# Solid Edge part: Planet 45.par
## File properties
Title: Planet 45
Author: DESYS
Template: Normal.par
Last saved by: PIM_1
Revision: 18
Application: Solid Edge
Tipo di contenuto documento: 0
Precisione: 0,990
Document Number: 8100
Revision: 0
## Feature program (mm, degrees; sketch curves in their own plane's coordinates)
sketch for "unnamed RevolvedProtrusion 1" plane through (0, 0, 0) normal (1, 0, 0) x-axis (0, 1, 0)
  line (0, 0) -> (-150, 0)
  arc centre (204.6477, -225) radius 420 from (-150, 0) to (-150, -450) ccw
  line (0, -450) -> (-150, -450)
revolve "unnamed RevolvedProtrusion 1" add full turn 360 deg about sketch line (0, -450) -> (0, 0)
sketch for "unnamed Cutout 1" plane through (0, 0, 0) normal (1, 0, 0) x-axis (0, 1, 0)
  line (-150, 0) -> (256.3931, -170)
extrude "unnamed Cutout 1" cut through
sketch for "unnamed Cutout 2" plane through (0, 0, 0) normal (1, 0, 0) x-axis (0, 1, 0)
  line (-289.0701, -170) -> (150, -450)
  dimension (linear) = 289.0701
extrude "unnamed Cutout 2" cut through
lofted cutout "unnamed LoftedCutout 1"
sketch for "ExtrudedProtrusion_1" plane through (0, 0, -20) normal (0, 0, 1) x-axis (1, 0, 0)
  line (115, -240) -> (115, -111.0081)
  line (-115, -240) -> (115, -240)
  line (-115, -240) -> (-115, -111.0081)
  dimension (linear) = 115
extrude "ExtrudedProtrusion_1" add finite 269.9862 along -normal
sketch for "Foro_1" plane through (0, -204.5382, -20) normal (0, 0, 1) x-axis (0, 1, 0)
  hole centre (14.5382, 0) bore radius 17.5
hole "Foro_1" diameter 35 through
sketch for "ExtrudedCutout_3" plane through (0, 0, 0) normal (1, 0, 0) x-axis (0, 1, 0)
  line (31.771, -213.9421) -> (95.2508, -415.0858)
  line (-99.0796, -213.9421) -> (31.771, -213.9421)
  line (-145, -35) -> (-99.0796, -213.9421)
  line (-225, -35) -> (-145, -35)
  line (-225, -35) -> (-225, -249.6187)
  dimension (linear) = 225
extrude "ExtrudedCutout_3" cut finite 190 symmetric
sketch for "unnamed Cutout 3" plane through (115, -197.1931, -174.9931) normal (1, 0, 0) x-axis (0, 1, 0)
  line (356.26, -280.789) -> (15.3699, -63.3995)
  arc centre (-193.0261, -211.6399) radius 255.7423 from (15.3699, -63.3995) to (-42.8069, -4.6657) ccw
extrude "unnamed Cutout 3" cut through along -normal
fillet "Rotondo_2" radius 90
fillet "Rotondo_3" radius 50
fillet "Rotondo_4" radius 15
sketch for "ExtrudedProtrusion_2" plane through (0, -43.9675, -213.9421) normal (0, 0, -1) x-axis (0, 1, 0)
  circle centre (-6.0325, 0) radius 35
extrude "ExtrudedProtrusion_2" add finite 80 along +normal
sketch for "ExtrudedCutout_6" plane through (0, -50, -293.9421) normal (0, 0, -1) x-axis (1, 0, 0)
  circle centre (0, 0) radius 24.5286
extrude "ExtrudedCutout_6" cut finite 800 along -normal
fillet "Rotondo_6" radius 15
sketch for "ExtrudedProtrusion_3" plane through (0, 0, 0) normal (1, 0, 0) x-axis (0, 1, 0)
  line (-91.9423, -267.0478) -> (-78.5367, -268.9499)
  line (-80.6987, -208.2144) -> (-78.5367, -268.9499)
  line (-121.1922, -30.6357) -> (-80.6987, -208.2144)
  line (-158.0507, -30.6357) -> (-121.1922, -30.6357)
  line (-158.0507, -30.6357) -> (-125.8286, -233.7128)
  arc centre (-86.3228, -227.4445) radius 40 from (-125.8286, -233.7128) to (-91.9423, -267.0478) ccw
extrude "ExtrudedProtrusion_3" add finite 40 symmetric
sketch for "unnamed Cutout 4" plane through (0, -240, -122.9938) normal (0, -1, 0) x-axis (1, 0, 0)
extrude "unnamed Cutout 4" cut through
sketch for "unnamed Cutout 5" #1 plane through (0, -240, -122.9938) normal (0, -1, 0) x-axis (1, 0, 0)
  line (60, 62.9938) -> (60, 72.9938)
  line (40, 72.9938) -> (40, 62.9938)
sketch for "unnamed Cutout 5" #2 plane through (0, -240, -122.9938) normal (0, -1, 0) x-axis (1, 0, 0)
  line (-50, 62.9938) -> (-40, 62.9938)
  line (-40, 82.9938) -> (-50, 82.9938)
  dimension (linear) = 50
  dimension (linear) = 50
extrude "unnamed Cutout 5" cut through along -normal
sketch for "ExtrudedCutout_9" plane through (-0.1325, -39.6447, -329.0615) normal (0, -0.537684, -0.843146) x-axis (0, 0.843146, -0.537684)
  line (-169.9069, -114.8675) -> (-10.3347, -114.8675)
  bspline degree 3 poles (149.8015, -4.8675) (149.8046, -12.0052) (148.8083, -19.4097) (144.5593, -34.1545) (141.3116, -41.4824) (132.668, -55.503) (127.277, -62.1951) (114.6742, -74.5758) (107.4624, -80.2644) (91.669, -90.4075) (83.0852, -94.863) (65.099, -102.4153) (55.6967, -105.5121) (36.6563, -110.3534) (27.018, -112.0979) (8.0292, -114.3547) (-1.3214, -114.867) (-10.3347, -114.8675) knots 0 0.125 0.25 0.375 0.5 0.625 0.75 0.875 1 multiplicities 4 2 2 2 2 2 2 2 4
  line (149.8015, 5.1325) -> (149.8015, -4.8675)
  bspline degree 3 poles (-10.3347, 115.1325) (-1.3214, 115.132) (8.0292, 114.6197) (27.018, 112.3629) (36.6563, 110.6184) (55.6967, 105.777) (65.099, 102.6803) (83.0852, 95.1279) (91.669, 90.6724) (107.4624, 80.5294) (114.6742, 74.8407) (127.277, 62.46) (132.668, 55.768) (141.3116, 41.7473) (144.5593, 34.4195) (148.8083, 19.6747) (149.8046, 12.2701) (149.8015, 5.1325) knots 0 0.125 0.25 0.375 0.5 0.625 0.75 0.875 1 multiplicities 4 2 2 2 2 2 2 2 4
  line (-169.9069, 115.1325) -> (-10.3347, 115.1325)
  line (-169.9069, 115.1325) -> (-169.9069, 220.6808)
  line (-169.9069, 220.6808) -> (238.9114, 220.6808)
  line (238.9114, 220.6808) -> (234.9328, -219.2448)
  line (-169.9069, -219.2448) -> (234.9328, -219.2448)
  line (-169.9069, -114.8675) -> (-169.9069, -219.2448)
extrude "ExtrudedCutout_9" cut finite 10 along -normal
sketch for "Foro_3" plane through (0, 0, 0) normal (0, -1, 0) x-axis (1, 0, 0)
  hole centre (0, -140) bore radius 10
hole "Foro_3" diameter 20 finite
fillet "Rotondo_8" radius 10
fillet "Rotondo_10" radius 8
fillet "Rotondo_11" radius 8
fillet "Rotondo_12" radius 8
fillet "Rotondo_13" radius 6
fillet "Rotondo_16" radius 3
fillet "Rotondo_17" radius 5
fillet "Rotondo_18" radius 5
fillet "Rotondo_19" radius 10
fillet "Rotondo_20" radius 10
fillet "Rotondo_21" radius 5
sketch for "unnamed RevolvedCutout 1" plane through (0, 0, 0) normal (1, 0, 0) x-axis (0, 1, 0)
  line (86.8578, -415.2753) -> (86.8578, -452.7436)
  line (86.8578, -452.7436) -> (304.8943, -452.7436)
  line (304.8943, -452.7436) -> (304.8943, -289.7689)
  line (210.3282, -289.7689) -> (304.8943, -289.7689)
  arc centre (59.1306, -264.511) radius 153.2928 from (210.3282, -289.7689) to (86.8578, -415.2753) cw
revolve "unnamed RevolvedCutout 1" cut full turn 360 deg
fillet "Rotondo_22" radius 10
fillet "Rotondo_23" radius 2
fillet "Rotondo_24" radius 2
sketch for "unnamed Protrusion 1" plane through (1.966, -27.3945, -325.0132) normal (0, -0.537684, -0.843146) x-axis (0, 0.843146, -0.537684)
extrude "unnamed Protrusion 1" add to key point along +normal
fillet "Rotondo_28" radius 8
fillet "Rotondo_29" radius 8
fillet "Rotondo_30" radius 8
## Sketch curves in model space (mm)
arc centre (0, -46.4938, 247.2167) radius 447.7105 from (0, -25.4714, -200) through (0, 81.4854, -181.8125) to (0, 180.927, -138.4315)
circle centre (0, -50, -200) radius 24.5286
closed spline through (-0.0002, -122.3239, -11.5773), (155.1873, 36.9873, -78.2195), (-15.4196, 180.1833, -138.1204), (-153.6786, 7.769, -65.997)
